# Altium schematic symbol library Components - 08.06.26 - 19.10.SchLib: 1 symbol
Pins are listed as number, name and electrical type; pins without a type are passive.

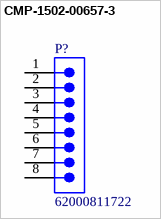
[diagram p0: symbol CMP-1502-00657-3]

## CMP-1502-00657-3
designator P?, comment 62000811722
WR-WTB Wire-to-Board Connectors 2.00 mm; Insulation Resistance: 1GΩ; Current Rating: 2A; Gender: Male; Pitch: 2mm
footprint 62000811722 (2.00mm Male Horizontal Shrouded Header, 8p)
pins: 1, 2, 3, 4, 5, 6, 7, 8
